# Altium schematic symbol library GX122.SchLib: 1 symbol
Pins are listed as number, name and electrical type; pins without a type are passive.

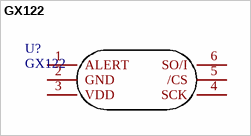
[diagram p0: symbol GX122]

## GX122
designator U?
footprint SOT-23-6
pins: 1 ALERT, 2 GND, 3 VDD, 4 SCK, 5 /CS, 6 SO/I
